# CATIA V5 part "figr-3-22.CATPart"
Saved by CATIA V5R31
Part number: Part1
Bounding box of the stored display mesh (mm): x -100.656 to 120.085, y -71.941 to 77.746, z 0 to 0
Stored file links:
  D:\PROJECTS\Project 2021\US EDITION\CATIA V5 6R 2021\Resources\Part Files\c03_catia_v5_6r2021_prt\figr-3-22.CATPart
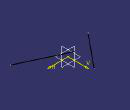
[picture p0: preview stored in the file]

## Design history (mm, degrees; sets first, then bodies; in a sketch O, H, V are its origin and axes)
Body1 (main body)
  Sketch1 on xy-plane, origin (0, 0, 0), H (1, 0, 0), V (0, 1, 0)
    line L1 (-9.7143, 77.7457) -> (-100.6564, -33.7935)
    line L2 (-27.4893, -3.1098) -> (120.0849, -71.9407)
